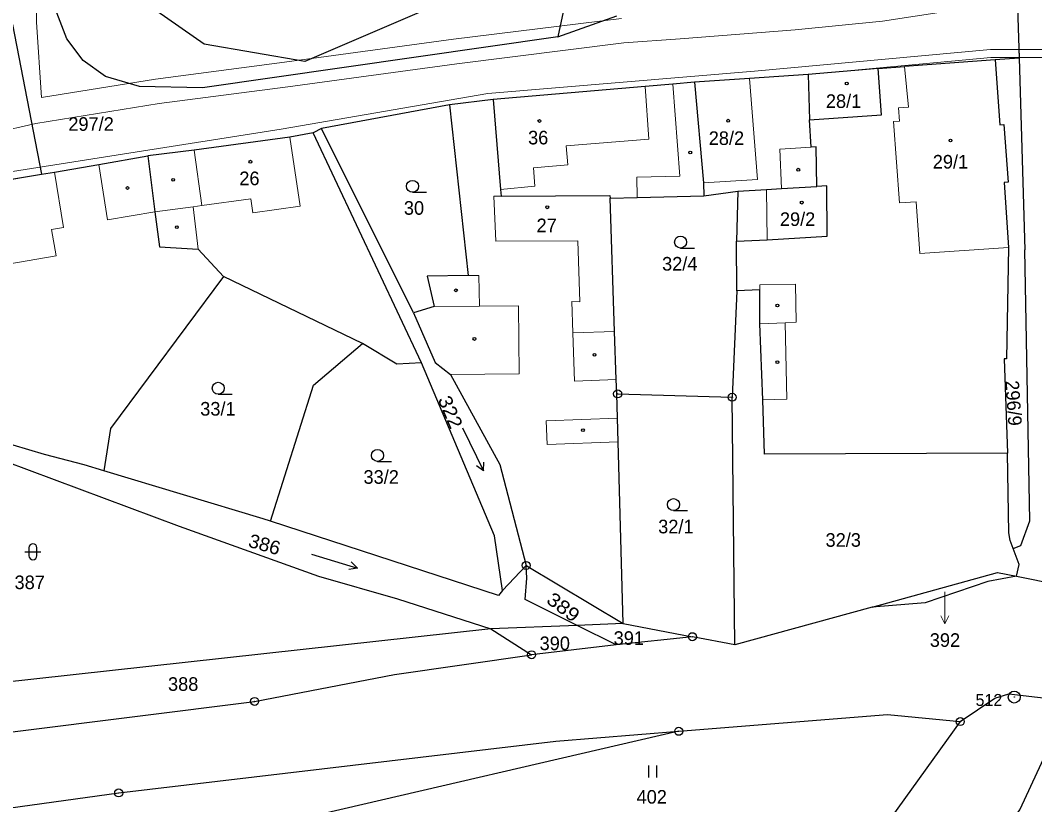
# Model space of a CAD drawing. Extents: x -769392 to -767038, y -1018329 to -1015269.
# Drawn here: x -768574.3 to -768447.4, y -1016436.2 to -1016338.1 of the extents above; entities that cross this region are included whole.
import ezdxf
from ezdxf.enums import TextEntityAlignment as Align

# ---------------------------------------------------------------- set-up
doc = ezdxf.new("R2010")
doc.units = 0
doc.header["$LTSCALE"] = 0.68
for name, color, linetype, lineweight in [('1', 7, 'Continuous', 25), ('13', 7, 'Continuous', 13), ('3', 7, 'Continuous', 25), ('4', 7, 'Continuous', 13), ('5', 7, 'Continuous', 25), ('7', 7, 'Continuous', 13), ('8', 7, 'Continuous', 25)]:
    doc.layers.add(name, color=color, linetype=linetype, lineweight=lineweight)
doc.layers.add('2', color=7, linetype='Continuous')

msp = doc.modelspace()

# ---------------------------------------------------------------- linework, layer by layer
at = {"layer": '1'}
for p, q in [((-768449.71, -1016331.77), (-768449.35, -1016342.79)), ((-768517.25, -1016334.01), (-768538.7, -1016343.21)), ((-768506.25, -1016336.41), (-768507.07, -1016340.13)), ((-768568.44, -1016340.39), (-768569.72, -1016337.14)), ((-768551.28, -1016341.04), (-768557.2, -1016336.94)), ((-768507.07, -1016340.13), (-768499.68, -1016337.53)), ((-768575.23, -1016338.61), (-768571.6, -1016357.31)), ((-768566.43, -1016343.09), (-768568.44, -1016340.39)), ((-768507.07, -1016340.13), (-768551.5, -1016346.53)), ((-768538.7, -1016343.21), (-768551.28, -1016341.04)), ((-768563.62, -1016345.11), (-768566.43, -1016343.09)), ((-768452.34, -1016343.01), (-768463.68, -1016343.86)), ((-768449.35, -1016342.79), (-768452.34, -1016343.01)), ((-768452.34, -1016343.01), (-768451.77, -1016351.15)), ((-768449.35, -1016342.79), (-768448.65, -1016366.78)), ((-768466.99, -1016344.09), (-768475.74, -1016344.86)), ((-768466.99, -1016344.09), (-768463.68, -1016343.86)), ((-768466.56, -1016349.9), (-768466.99, -1016344.09)), ((-768559.37, -1016346.35), (-768563.62, -1016345.11)), ((-768483.07, -1016345.36), (-768489.95, -1016345.81)), ((-768475.74, -1016344.86), (-768483.07, -1016345.36)), ((-768475.74, -1016344.86), (-768475.58, -1016350.51)), ((-768551.5, -1016346.53), (-768559.37, -1016346.35)), ((-768496.14, -1016346.37), (-768515.13, -1016347.97)), ((-768492.67, -1016346.08), (-768496.14, -1016346.37)), ((-768489.95, -1016345.81), (-768492.67, -1016346.08)), ((-768489.95, -1016345.81), (-768488.85, -1016358.42)), ((-768515.13, -1016347.97), (-768520.61, -1016348.65)), ((-768515.13, -1016347.97), (-768514.22, -1016359.23)), ((-768520.61, -1016348.65), (-768536.59, -1016351.62)), ((-768520.61, -1016348.65), (-768518.27, -1016370)), ((-768475.58, -1016350.51), (-768466.56, -1016349.9)), ((-768475.38, -1016353.93), (-768475.58, -1016350.51)), ((-768536.59, -1016351.62), (-768537.63, -1016352.13)), ((-768525.09, -1016374.67), (-768536.59, -1016351.62)), ((-768451.77, -1016351.15), (-768451.26, -1016351.12)), ((-768451.26, -1016351.12), (-768450.75, -1016358.33)), ((-768540.56, -1016352.68), (-768552.51, -1016354.31)), ((-768537.63, -1016352.13), (-768540.56, -1016352.68)), ((-768524.12, -1016380.93), (-768537.63, -1016352.13)), ((-768552.51, -1016354.31), (-768558.32, -1016355.04)), ((-768474.73, -1016353.89), (-768475.38, -1016353.93)), ((-768474.67, -1016358.85), (-768474.73, -1016353.89)), ((-768564.44, -1016356.09), (-768558.32, -1016355.04)), ((-768558.32, -1016355.04), (-768557.46, -1016362.03)), ((-768571.6, -1016357.31), (-768570.01, -1016357.07)), ((-768570.01, -1016357.07), (-768564.44, -1016356.09)), ((-768594.29, -1016361.09), (-768571.6, -1016357.31)), ((-768450.75, -1016358.33), (-768451.25, -1016358.37)), ((-768451.25, -1016358.37), (-768450.68, -1016366.5)), ((-768514.22, -1016359.23), (-768514.15, -1016360.06)), ((-768488.85, -1016358.42), (-768488.81, -1016360.02)), ((-768488.81, -1016360.02), (-768484.55, -1016359.43)), ((-768484.55, -1016359.43), (-768484.69, -1016365.7)), ((-768484.55, -1016359.43), (-768480.94, -1016359.24)), ((-768480.94, -1016359.24), (-768479.09, -1016359.13)), ((-768479.09, -1016359.13), (-768474.67, -1016358.85)), ((-768473.41, -1016358.77), (-768474.67, -1016358.85)), ((-768473.36, -1016365.09), (-768473.41, -1016358.77)), ((-768514.15, -1016360.06), (-768500.55, -1016359.98)), ((-768500.55, -1016359.98), (-768500.52, -1016360.31)), ((-768500.52, -1016360.31), (-768497.11, -1016360.23)), ((-768499.95, -1016376.98), (-768500.52, -1016360.31)), ((-768497.11, -1016360.23), (-768488.81, -1016360.02)), ((-768557.46, -1016362.03), (-768556.88, -1016366.42)), ((-768484.69, -1016365.7), (-768480.86, -1016365.54)), ((-768484.68, -1016371.91), (-768484.69, -1016365.7)), ((-768480.86, -1016365.54), (-768473.36, -1016365.09)), ((-768556.88, -1016366.42), (-768552.04, -1016366.7)), ((-768552.04, -1016366.7), (-768548.88, -1016370.1)), ((-768450.68, -1016366.5), (-768450.94, -1016380.43)), ((-768448.01, -1016400.69), (-768448.65, -1016366.78)), ((-768548.88, -1016370.1), (-768563, -1016389.15)), ((-768531.48, -1016378.49), (-768548.88, -1016370.1)), ((-768518.27, -1016370), (-768523.4, -1016370.07)), ((-768523.4, -1016370.07), (-768522.51, -1016373.88)), ((-768484.68, -1016371.91), (-768485.25, -1016385.23)), ((-768481.77, -1016371.78), (-768484.68, -1016371.91)), ((-768481.78, -1016376.04), (-768481.77, -1016371.78)), ((-768522.51, -1016373.88), (-768525.09, -1016374.67)), ((-768525.09, -1016374.67), (-768522.37, -1016380.88)), ((-768481.4, -1016385.53), (-768481.78, -1016376.04)), ((-768499.74, -1016383.02), (-768499.95, -1016376.98)), ((-768537.61, -1016383.73), (-768531.48, -1016378.49)), ((-768527.17, -1016381.07), (-768531.48, -1016378.49)), ((-768524.12, -1016380.93), (-768527.17, -1016381.07)), ((-768514.95, -1016402.55), (-768524.12, -1016380.93)), ((-768522.37, -1016380.88), (-768520.46, -1016382.38)), ((-768450.94, -1016380.43), (-768451.23, -1016380.41)), ((-768451.23, -1016380.41), (-768450.81, -1016392.22)), ((-768520.46, -1016382.38), (-768514.31, -1016393.63)), ((-768542.99, -1016400.74), (-768537.61, -1016383.73)), ((-768499.68, -1016384.8), (-768499.74, -1016383.02)), ((-768571.23, -1016392.4), (-768596.87, -1016384.66)), ((-768499.68, -1016384.8), (-768499.57, -1016384.8)), ((-768499.59, -1016387.83), (-768499.68, -1016384.8)), ((-768499.57, -1016384.8), (-768485.25, -1016385.23)), ((-768484.9, -1016416.17), (-768485.25, -1016385.23)), ((-768481.21, -1016392.35), (-768481.4, -1016385.53)), ((-768499.49, -1016390.79), (-768499.59, -1016387.83)), ((-768563, -1016389.15), (-768563.83, -1016394.43)), ((-768498.87, -1016413.54), (-768499.49, -1016390.79)), ((-768566.29, -1016393.69), (-768571.23, -1016392.4)), ((-768450.81, -1016392.22), (-768481.21, -1016392.35)), ((-768450.65, -1016402.2), (-768450.81, -1016392.22)), ((-768563.83, -1016394.43), (-768566.29, -1016393.69)), ((-768514.31, -1016393.63), (-768511.01, -1016406.26)), ((-768543.91, -1016400.44), (-768563.83, -1016394.43)), ((-768542.99, -1016400.74), (-768543.91, -1016400.44)), ((-768449.14, -1016403.77), (-768448.01, -1016400.69)), ((-768513.96, -1016409.4), (-768514.95, -1016402.55)), ((-768450.49, -1016403.15), (-768450.65, -1016402.2)), ((-768450.12, -1016404.13), (-768450.49, -1016403.15)), ((-768450.12, -1016404.13), (-768449.14, -1016403.77)), ((-768449.36, -1016406.14), (-768450.12, -1016404.13)), ((-768511.01, -1016406.26), (-768513.96, -1016409.4)), ((-768511.01, -1016406.26), (-768498.87, -1016413.54)), ((-768449.69, -1016407.59), (-768449.36, -1016406.14)), ((-768449.69, -1016407.59), (-768441.56, -1016409.26)), ((-768467.75, -1016411.46), (-768484.9, -1016416.17)), ((-768515.42, -1016414.21), (-768597.72, -1016423.25)), ((-768504.64, -1016413.77), (-768515.42, -1016414.21)), ((-768515.42, -1016414.21), (-768510.33, -1016417.43)), ((-768498.87, -1016413.54), (-768504.64, -1016413.77)), ((-768499.77, -1016416.2), (-768504.64, -1016413.77)), ((-768498.87, -1016413.54), (-768490.22, -1016415.17)), ((-768490.22, -1016415.17), (-768499.77, -1016416.2)), ((-768484.9, -1016416.17), (-768490.22, -1016415.17)), ((-768499.77, -1016416.2), (-768510.33, -1016417.43)), ((-768456.72, -1016425.79), (-768466.24, -1016439.01))]:
    msp.add_line(p, q, dxfattribs=at)
for points in [[(-768597.3, -1016385.07), (-768595.97, -1016385.47), (-768590.69, -1016389.34), (-768585.89, -1016390.17), (-768579.44, -1016391.99), (-768554.41, -1016401.35), (-768536.99, -1016407.59), (-768527.09, -1016410.45), (-768515.42, -1016414.21)], [(-768513.96, -1016409.4), (-768514.45, -1016410), (-768542.99, -1016400.74)], [(-768504.64, -1016413.77), (-768511.12, -1016410.53), (-768510.92, -1016407.87), (-768511.01, -1016406.26)], [(-768467.75, -1016411.46), (-768452.06, -1016407.14), (-768449.69, -1016407.59)], [(-768449.69, -1016407.59), (-768453.29, -1016408.28), (-768461.12, -1016410.92), (-768467.75, -1016411.46)], [(-768597.61, -1016430.31), (-768574.91, -1016427.03), (-768544.97, -1016423.27), (-768527.49, -1016419.91), (-768510.33, -1016417.43)], [(-768456.72, -1016425.79), (-768452.42, -1016422.86), (-768450.67, -1016422.31), (-768443.48, -1016423.15)], [(-768443.93, -1016425.28), (-768449.29, -1016436.8), (-768497.79, -1016498.96)], [(-768491.93, -1016427.01), (-768465.81, -1016424.92), (-768456.72, -1016425.79)], [(-768845.93, -1016484.91), (-768809.19, -1016473.29), (-768793.36, -1016469.31), (-768763.37, -1016464.27), (-768714.25, -1016457.68), (-768646.26, -1016446.91), (-768617.02, -1016442.83), (-768594.78, -1016439.25), (-768561.97, -1016434.72), (-768507.31, -1016428.23), (-768491.93, -1016427.01)], [(-768491.93, -1016427.01), (-768538.99, -1016437.9), (-768538.91, -1016446.63)]]:
    msp.add_lwpolyline(points, dxfattribs=at)
at = {"layer": '13'}
for points in [[(-768499.08, -1016337.83), (-768520.1, -1016340.42), (-768541.23, -1016343.31), (-768557.35, -1016345.42), (-768571.61, -1016347.72), (-768572.26, -1016338.32), (-768572.31, -1016323.42)], [(-768587.74, -1016354.48), (-768572.31, -1016350.97), (-768556.91, -1016348.48), (-768540.83, -1016346.39), (-768519.69, -1016343.5), (-768498.78, -1016340.91), (-768491.76, -1016340.39), (-768477.38, -1016339.28), (-768466.44, -1016338.2), (-768449.58, -1016335.6)], [(-768594.29, -1016361.09), (-768571.6, -1016357.31), (-768570.01, -1016357.07), (-768564.44, -1016356.09), (-768558.32, -1016355.04), (-768552.51, -1016354.31), (-768540.56, -1016352.68), (-768537.63, -1016352.13), (-768536.59, -1016351.62), (-768520.61, -1016348.65), (-768515.13, -1016347.97), (-768496.14, -1016346.37), (-768492.67, -1016346.08), (-768489.95, -1016345.81), (-768483.07, -1016345.36), (-768475.74, -1016344.86), (-768452.91, -1016342.72), (-768449.35, -1016342.72), (-768449.38, -1016341.72), (-768452.96, -1016341.72), (-768482.45, -1016344.45), (-768515.8, -1016347.22), (-768541.64, -1016351.71), (-768593.54, -1016359.85)]]:
    msp.add_lwpolyline(points, dxfattribs=at)
msp.add_lwpolyline([(-768440.91, -1016342.74), (-768440.95, -1016341.74), (-768449.38, -1016341.72), (-768449.35, -1016342.72)], close=True, dxfattribs=at)
at = {"layer": '3'}
for p, q in [((-768525.223, -1016359.59), (-768523.473, -1016359.59)), ((-768491.703, -1016366.56), (-768489.953, -1016366.56)), ((-768549.523, -1016384.85), (-768547.773, -1016384.85)), ((-768529.603, -1016393.24), (-768527.853, -1016393.24)), ((-768516.335, -1016394.446), (-768517.214, -1016393.787)), ((-768492.583, -1016399.4), (-768490.833, -1016399.4)), ((-768573.191, -1016404.041), (-768573.191, -1016405.042)), ((-768572.189, -1016405.042), (-768572.189, -1016404.041)), ((-768573.691, -1016404.541), (-768571.689, -1016404.541)), ((-768532.107, -1016406.59), (-768533.188, -1016406.784)), ((-768495.661, -1016432.77), (-768495.661, -1016431.27)), ((-768494.66, -1016432.77), (-768494.66, -1016431.27))]:
    msp.add_line(p, q, dxfattribs=at)
for points in [[(-768518.965, -1016389.053), (-768516.335, -1016394.446), (-768516.313, -1016393.347)], [(-768537.845, -1016404.836), (-768532.107, -1016406.59), (-768532.895, -1016405.825)]]:
    msp.add_lwpolyline(points, dxfattribs=at)
for centre in [(-768525.2229, -1016358.8398), (-768491.7029, -1016365.8098), (-768549.5229, -1016384.0998), (-768529.6029, -1016392.4898), (-768492.5829, -1016398.6498)]:
    msp.add_circle(centre, 0.75, dxfattribs=at)
for centre, start, end in [((-768572.69, -1016404.0409), 0, 180), ((-768572.69, -1016405.0409), 180, 359.98789)]:
    msp.add_arc(centre, 0.5, start, end, dxfattribs=at)
at = {"layer": '4'}
for p, q in [((-768463.68, -1016343.86), (-768463.19, -1016348.92)), ((-768482.07, -1016357.99), (-768483.07, -1016345.36)), ((-768495.65, -1016352.94), (-768496.14, -1016346.37)), ((-768492.67, -1016346.08), (-768491.78, -1016357.56)), ((-768463.19, -1016348.92), (-768464.45, -1016349.03)), ((-768464.45, -1016349.03), (-768464.34, -1016350.69)), ((-768464.34, -1016350.69), (-768465.09, -1016350.75)), ((-768465.09, -1016350.75), (-768464.34, -1016360.92)), ((-768540.56, -1016352.68), (-768539.26, -1016361.34)), ((-768506.01, -1016353.79), (-768495.65, -1016352.94)), ((-768551.55, -1016361.24), (-768552.51, -1016354.31)), ((-768505.78, -1016356.16), (-768506.01, -1016353.79)), ((-768475.38, -1016353.93), (-768479.29, -1016354.2)), ((-768479.29, -1016354.2), (-768479.09, -1016359.13)), ((-768568.88, -1016364), (-768570.01, -1016357.07)), ((-768564.44, -1016356.09), (-768563.38, -1016363.01)), ((-768510.1, -1016356.54), (-768505.78, -1016356.16)), ((-768509.91, -1016358.84), (-768510.1, -1016356.54)), ((-768491.78, -1016357.56), (-768497.18, -1016357.68)), ((-768497.18, -1016357.68), (-768497.11, -1016360.23)), ((-768488.85, -1016358.42), (-768482.07, -1016357.99)), ((-768514.22, -1016359.23), (-768509.91, -1016358.84)), ((-768480.94, -1016359.24), (-768480.86, -1016365.54)), ((-768545.46, -1016360.4), (-768551.55, -1016361.24)), ((-768545.21, -1016362.14), (-768545.46, -1016360.4)), ((-768514.15, -1016360.06), (-768515.07, -1016360.07)), ((-768515.07, -1016360.07), (-768514.81, -1016365.71)), ((-768464.34, -1016360.92), (-768462.24, -1016360.78)), ((-768462.24, -1016360.78), (-768461.79, -1016367.23)), ((-768563.38, -1016363.01), (-768557.46, -1016362.03)), ((-768552.67, -1016361.4), (-768557.46, -1016362.03)), ((-768551.55, -1016361.24), (-768552.67, -1016361.4)), ((-768552.67, -1016361.4), (-768552.04, -1016366.7)), ((-768539.26, -1016361.34), (-768545.21, -1016362.14)), ((-768570.37, -1016364.26), (-768568.88, -1016364)), ((-768569.79, -1016367.55), (-768570.37, -1016364.26)), ((-768514.81, -1016365.71), (-768504.53, -1016365.64)), ((-768504.53, -1016365.64), (-768504.32, -1016373.27)), ((-768461.79, -1016367.23), (-768450.68, -1016366.5)), ((-768594.45, -1016371.67), (-768569.79, -1016367.55)), ((-768516.95, -1016370.01), (-768518.27, -1016370)), ((-768516.84, -1016373.83), (-768516.95, -1016370.01)), ((-768481.77, -1016371.18), (-768477.33, -1016371.09)), ((-768477.33, -1016371.09), (-768477.24, -1016375.84)), ((-768481.77, -1016371.78), (-768481.77, -1016371.18)), ((-768505.29, -1016373.25), (-768505.18, -1016377.18)), ((-768504.32, -1016373.27), (-768505.29, -1016373.25)), ((-768516.84, -1016373.83), (-768522.51, -1016373.88)), ((-768511.99, -1016373.8), (-768516.84, -1016373.83)), ((-768511.88, -1016382.28), (-768511.99, -1016373.8)), ((-768478.63, -1016375.9), (-768481.78, -1016376.04)), ((-768477.24, -1016375.84), (-768478.63, -1016375.9)), ((-768478.63, -1016375.9), (-768478.42, -1016385.47)), ((-768505.18, -1016377.18), (-768499.95, -1016376.98)), ((-768505.18, -1016377.18), (-768504.98, -1016383.22)), ((-768520.46, -1016382.38), (-768511.88, -1016382.28)), ((-768504.98, -1016383.22), (-768499.74, -1016383.02)), ((-768478.42, -1016385.47), (-768481.4, -1016385.53)), ((-768508.5, -1016388.16), (-768499.59, -1016387.83)), ((-768508.37, -1016391.13), (-768508.5, -1016388.16)), ((-768499.49, -1016390.79), (-768508.37, -1016391.13))]:
    msp.add_line(p, q, dxfattribs=at)
at = {"layer": '5'}
for centre in [(-768470.9268, -1016345.9692), (-768509.3568, -1016350.6692), (-768485.7468, -1016350.6292), (-768457.9568, -1016353.0992), (-768490.4868, -1016354.6192), (-768545.4968, -1016355.7592), (-768476.9768, -1016356.7592), (-768555.1468, -1016358.0192), (-768560.8768, -1016359.0492), (-768476.5568, -1016360.8792), (-768508.3668, -1016361.4592), (-768554.6868, -1016363.9392), (-768519.7868, -1016371.8492), (-768479.5968, -1016373.7392), (-768517.4868, -1016377.9292), (-768502.4568, -1016379.9292), (-768479.5968, -1016380.8292), (-768503.9068, -1016389.3492)]:
    msp.add_circle(centre, 0.175, dxfattribs=at)
at = {"layer": '7'}
msp.add_line((-768458.64, -1016413.571), (-768458.139, -1016412.57), dxfattribs=at)
msp.add_lwpolyline([(-768458.64, -1016409.56), (-768458.64, -1016410.57), (-768458.64, -1016413.571), (-768459.141, -1016412.57)], dxfattribs=at)
at = {"layer": '8'}
for centre, radius in [((-768499.57, -1016384.7999), 0.5), ((-768499.57, -1016384.7999), 0.0303), ((-768485.25, -1016385.2299), 0.5), ((-768485.25, -1016385.2299), 0.0303), ((-768511.01, -1016406.2599), 0.5), ((-768511.01, -1016406.2599), 0.0303), ((-768490.22, -1016415.1699), 0.5), ((-768490.22, -1016415.1699), 0.0303), ((-768510.33, -1016417.4299), 0.5), ((-768510.33, -1016417.4299), 0.0303), ((-768544.97, -1016423.2699), 0.5), ((-768449.97, -1016422.7198), 0.75), ((-768449.97, -1016422.7198), 0.03), ((-768544.97, -1016423.2699), 0.0303), ((-768456.72, -1016425.7899), 0.5), ((-768491.93, -1016427.0099), 0.5), ((-768456.72, -1016425.7899), 0.0303), ((-768491.93, -1016427.0099), 0.0303), ((-768561.97, -1016434.7199), 0.5), ((-768561.97, -1016434.7199), 0.0303)]:
    msp.add_circle(centre, radius, dxfattribs=at)

# ---------------------------------------------------------------- texts
at = {"layer": '2'}
for s, p in [('28/1', (-768471.319, -1016349.035)), ('297/2', (-768565.42, -1016351.895)), ('36', (-768509.509, -1016353.595)), ('28/2', (-768485.969, -1016353.665)), ('29/1', (-768457.949, -1016356.615)), ('26', (-768545.619, -1016358.695)), ('30', (-768525.039, -1016362.395)), ('29/2', (-768477.069, -1016363.795)), ('27', (-768508.449, -1016364.575)), ('32/4', (-768491.799, -1016369.375)), ('33/1', (-768549.559, -1016387.515)), ('33/2', (-768529.139, -1016396.045)), ('32/1', (-768492.289, -1016402.245)), ('32/3', (-768471.359, -1016403.925)), ('392', (-768458.639, -1016416.445))]:
    msp.add_text(s, height=1.7, dxfattribs=at).set_placement(p, align=Align.CENTER)
msp.add_text('296/9', height=1.7, rotation=274, dxfattribs=at).set_placement((-768450.901, -1016386.0097), align=Align.CENTER)
at = {"layer": '2', "width": 1.1}
msp.add_text('322', height=1.7, rotation=293, dxfattribs=at).set_placement((-768521.2693, -1016387.4049), align=Align.CENTER)
at = {"layer": '2'}
for s, rotation, width, p in [('386', 344, 1.05, (-768545.867, -1016403.898)), ('389', 323, 1.15, (-768508.615, -1016410.839))]:
    msp.add_text(s, height=1.7, rotation=rotation, dxfattribs=dict(at, width=width)).set_placement(p)
for s, p in [('387', (-768574.99, -1016409.225)), ('390', (-768509.33, -1016416.855)), ('391', (-768500.07, -1016416.195)), ('388', (-768555.8, -1016421.945)), ('402', (-768497.2, -1016436.055))]:
    msp.add_text(s, height=1.7, dxfattribs=at).set_placement(p)
at = {"layer": '8'}
msp.add_text('512', height=1.5, dxfattribs=at).set_placement((-768451.469, -1016423.837), align=Align.RIGHT)

doc.saveas('drawing.dxf')
